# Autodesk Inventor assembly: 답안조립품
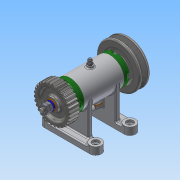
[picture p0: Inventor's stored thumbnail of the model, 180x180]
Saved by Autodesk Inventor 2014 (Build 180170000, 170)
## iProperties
Created: 2015-11
Part Number: 답안조립품
Document SubType Name: Assembly
Designer: 03
Author: 03
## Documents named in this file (16)
- C:\Users\03\Desktop\451110V1014\답안조립품.iam
- C:\Users\03\Desktop\451110V1014\1-본체.ipt
- C:\Users\03\Desktop\451110V1014\니플 M 6 x 0.75.ipt
- C:\Users\03\Desktop\451110V1014\볼트 M 6 x 8.ipt
- C:\Users\03\Desktop\451110V1014\와셔 6x11.5.ipt
- C:\Users\03\Desktop\451110V1014\축.ipt
- C:\Users\03\Desktop\451110V1014\베어링 15 x 32 x 9.ipt
- C:\Users\03\Desktop\451110V1014\스프링와셔 8.ipt
- C:\Users\03\Desktop\451110V1014\오일 실 15 25 7.ipt
- C:\Users\03\Desktop\451110V1014\와셔 8x17.ipt
- C:\Users\03\Desktop\451110V1014\커버.ipt
- C:\Users\03\Desktop\451110V1014\키 3 x 3 x 12.ipt
- C:\Users\03\Desktop\451110V1014\V벨트풀리.ipt
- C:\Users\03\Desktop\451110V1014\스퍼기어.ipt
- C:\Users\03\Desktop\451110V1014\너트 M 8.ipt
- C:\Users\03\Desktop\451110V1014\볼트 M4 x 12.ipt
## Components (12 placed, 4 different names)
1. 1-본체:1
2. KS B 2023 6002 - 15 x 32 x 9:1
3. KS B 2023 6002 - 15 x 32 x 9:2
4. V벨트풀리:1 — 각도:4
5. ISO 4762 M4 x 12:2
6. ISO 4762 M4 x 12:3
7. ISO 4762 M4 x 12:4
8. ISO 4762 M4 x 12:5
9. ISO 4762 M4 x 12:1
10. ISO 4762 M4 x 12:6
11. ISO 4762 M4 x 12:7
12. ISO 4762 M4 x 12:8
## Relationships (1: Angle 1)
- 각도:4 [Angle]: V벨트풀리:1
